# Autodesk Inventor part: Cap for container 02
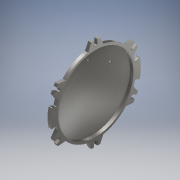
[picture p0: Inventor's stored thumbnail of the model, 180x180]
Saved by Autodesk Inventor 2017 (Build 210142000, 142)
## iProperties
Created: 2020-03
Part Number: Cap for container 02
Material: Stainless Steel
Document SubType Name: Modeling
Designer: user
Density: 8 g/cm^3
Appearance: Semi-Polished
Author: user
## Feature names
1. Revolution1
2. Extrusion1
3. Fillet1
4. Fillet2
5. Extrusion2
6. Circular Pattern1
7. Extrusion3
8. Fillet3
9. Sweep1
10. Circular Pattern2
## Parameters: d3 = 2 mm, d4 = 2 mm, d5 = 90 deg, d6 = 208 mm, d7 = 8 mm, d8 = 0, d9 = 2 mm, d10 = 2 mm, d14 = 50 deg, d15 = 9 mm, d16 = 9 mm, d17 = 8 mm, d18 = 0, d20 = 360 deg, d22 = 235 mm, d25 = 8 mm, d26 = 0, d27 = 2 mm, d28 = 6 mm, d29 = 0, d30 = 0, d32 = 0, d34 = 60 deg
